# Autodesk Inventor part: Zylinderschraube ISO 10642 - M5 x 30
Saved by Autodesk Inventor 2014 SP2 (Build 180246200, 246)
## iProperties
Created: 2015-07
Part Number: Zylinderschraube ISO 10642 - M5 x 30
Material: Generisch
Document SubType Name: Modeling
Designer: e_krauts
Density: 1 g/cm^3
Appearance: Vorgabe
Mass: 0.665096 g
Surface Area: 6.25597 cm^2
Volume: 0.665096 cm^3
Sending System: SolidWorks 2011
Last Author: e_boekem
Sachnummer: IS0 10642 M5x30
Einheit: Stck.
Author: e_krauts
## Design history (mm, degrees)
node "Zylinderschraube ISO 10642 - M5 x 30.ipt1"
node "Hex"
node "Basis1"
